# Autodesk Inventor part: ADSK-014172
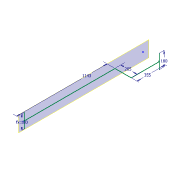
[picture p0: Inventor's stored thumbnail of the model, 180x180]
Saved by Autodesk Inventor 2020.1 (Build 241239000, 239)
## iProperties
Created: 2019-10
Part Number: ADSK-014172
Material: 1.0501 C35
Document SubType Name: Modeling
Designer: lutzd
Density: 7.84 g/cm^3
Appearance: Stahl
VLDS_Profile: Default Part
VLDS_TimeStamp: 2016-07-29
VLDS_FailCnt: 0
VLDS_AcceptCnt: 0
Dimensions: 0x0x0 mm
Mass: 0 kg
DocNumber: ADSK-014172
Folder: 01 - Themengebiete\Simplification\01 - Packaging machine\
VDS_Category: 3D Komponenten
VDS_NumSchm: Autodesk
Title: skeleton
Author: lutzd
Revision Number: -
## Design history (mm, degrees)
sketch "Skizze1"
  geometry: L1 (0, 0)-(0, -355); L2 (0, -355)-(-205, -355); L3 (-205, -355)-(-205, -1498); 1 further point
  constraints: 6 end point, 2 perpendicular, 1 coincident, 1 vertical
  dimensions: "d0" = 355 distance of L1.start L1.end; "d1" = 205 distance of L1.end L2.end; "d2" = 1143 distance of L2.end L3.end
sketch "Skizze2"
  geometry: L1 (0, 90)-(0, -90); 2 further points
  constraints: 2 end point, 1 coincident, 1 midpoint, 1 vertical
  dimensions: "d9" = 180 distance of L1.start L1.end
workplane "Arbeitsebene1"
sketch "Skizze3"
  geometry: L1 (1143, 90)-(1143, -90); 3 further points
  constraints: 2 end point, 1 coincident, 1 midpoint, 1 vertical
  dimensions: "d11" = 180 distance of L1.start L1.end (= d9)
other parameters: "d10" = 90 deg
